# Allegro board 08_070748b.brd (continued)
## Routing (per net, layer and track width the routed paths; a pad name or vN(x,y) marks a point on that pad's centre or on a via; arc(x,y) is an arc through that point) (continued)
GND_POWER: length 1047
  TOP w0.203: 92.23,78.26 v2(92.26,78.26) 92.26,78.3 ; v2(89.26,81.26) 89.26,81.26
  LAYER_4 w0.254: v1(171.32,15.75) 170.43,14.86 170.43,14.22 173.99,10.67 J2.2 ; J1.4 179.32,148.84 178.94,148.46 178.94,147.32 175.51,143.89 175.51,139.57 v1(176.4,138.68) ; 124.33,10.8 124.33,13.21 106.05,31.5 CO29.1 106.93,67.44 v1(106.93,67.56) ; 7.95,76 7.19,76 ; J3.5 124.33,144.65 107.44,127.76 107.44,92.33 v1(106.93,91.82)
  LAYER_4 w0.508: P5.11 220.09,5.07 220.09,10.02 219.84,10.28 219.84,141.23 220.85,142.25 220.85,152.87 220.35,153.38 P4.11 P4.12 ; J2.2 J2.3 J2.4 J2.5 ; 220.31,4.83 220.31,2.83 ; 124.33,10.8 J6.2 J6.5 J6.4 J6.3 ; J3.4 J3.3 J3.2 J3.5 ; J1.5 J1.2 J1.3 J1.4
  LAYER_5 w0.254: v1(155.32,86.11) 155.45,86.11 156.46,85.09 168.28,85.09 168.91,85.72 v1(169.67,85.72) ; v1(106.05,67.56) 106.05,67.44 106.55,66.93 108.84,66.93 109.98,65.79 130.56,65.79 149.1,47.24 149.1,46.48 149.35,46.23 150.5,46.23 154.18,49.91 183.51,49.91 192.15,41.27 192.15,32.55 v1(192.19,32.51) ; J4.5 186.56,79.88 180.97,79.88 180.32,80.53 109.84,80.53 108.39,81.98 107.12,81.98 v1(107.06,82.04) ; J5.2 191.13,73.03 185.8,78.36 109.22,78.36 107.82,76.96 v1(107.06,76.96) ; v1(191.77,127.63) 191.64,127.51 191.64,113.41 189.87,111.63 167.39,111.63 164.72,108.97 154.56,108.97 151.89,111.63 148.34,111.63 139.83,103.12 120.65,103.12 110.87,93.34 105.41,93.34 105.03,92.96 v1(105.03,91.82)
  LAYER_5 w0.508: J5.2 J5.3 J5.4 J5.5 ; J4.5 J4.4 J4.3 J4.2
  LAYER_6 w0.254: v1(106.17,76.96) 106.86,77.85 107.82,77.85 108.08,77.6 108.08,76.96 109.35,75.69 v1(178.05,75.69) ; v1(178.05,83.19) 177.04,84.2 109.73,84.2 108.2,82.68 108.2,81.79 107.57,81.15 106.3,81.15 106.17,81.28 v1(106.17,82.04)
  BOTTOM w0.203: R74.2 176.66,138.43 v1(176.4,138.68) ; v1(83.44,65.66) 82.7,65.66 82.17,66.19 CIN11.1 v1(81.92,66.29) ; U3.7 v1(235.13,74.75) ; v1(226.44,115.7) 227.12,116.37 R182.1
  BOTTOM w0.254: v1(171.32,15.75) 171.45,15.88 R75.2 ; v1(178.05,75.69) 178.73,75.69 R20.2 ; v1(106.17,82.04) CO10.1 106.68,81.03 107.06,81.41 v1(107.06,82.04) ; R62.2 v1(191.77,127.63) ; 8.25,75.95 v1(7.11,75.95) ; R9.2 v1(192.19,32.51) ; CO37.1 170.43,86.49 v1(169.67,85.72) ; 76.33,79.76 v1(77.09,79.76) ; R122.1 v1(155.32,86.11) ; R64.2 v1(178.05,83.19)
  BOTTOM w0.305: v1(105.03,91.82) 105.03,92.71 105.16,92.84 CO2.1 106.43,92.84 106.93,92.33 v1(106.93,91.82) ; v1(106.05,67.56) CO29.1 106.93,67.44 v1(106.93,67.56)
  BOTTOM w0.381: R144.1 v1(195.07,11.52) ; v1(107.06,76.96) 107.06,77.6 106.68,77.98 CO20.1 v1(106.17,76.96) ; R183.1 226.86,109.35 226.86,109.01 v1(226.57,108.71) ; Q5.2 v1(90.5,146.81) ; v1(93.85,149.22) 94.59,149.22 94.95,148.87 Q8.2 ; J6.3 128.49,12.87 C74.2 ; R134.1 v1(83.95,11.64)
  BOTTOM w0.508: C71.2 128.74,146.9 J3.4 ; C73.2 197.19,75.22 J5.3 ; R180.1 v1(194.06,150.5) ; C91.1 v1(12.87,29.04) ; 227.08,138.18 v1(227.09,138.19) R181.1 ; v2(83.27,76.26) 83.07,76.45 CIN13.1 ; Q13.2 v1(93.04,8.71) ; CIN14.1 83.02,72.01 v2(83.27,72.26) ; 81.28,149.22 v1(81.28,150.24) ; C89.1 v1(12.87,143.34) ; v2(83.27,88.26) 83.26,88.27 CIN10.1 ; CIN9.1 82.94,82.93 v2(83.27,83.26) ; C72.2 198.46,95.16 199.52,94.11 J4.3 ; R52.2 v1(22.86,151.38)
  vias: v1(7.11,77.09) v1(7.11,74.8) v1(9.4,77.09) v1(9.4,75.95) v1(9.4,74.8) v1(12.23,124.46) v1(12.23,10.16) v1(16.64,77.09) v1(16.64,75.95) v1(16.64,74.8) v1(18.92,77.09) v1(18.92,75.95) v1(18.92,74.8) v1(25.53,112.14) v1(25.53,111) v1(25.53,109.86) v1(25.53,49.78) v1(25.53,48.64) v1(25.53,47.5) v1(27.81,112.14) v1(27.81,111) v1(27.81,109.86) v1(27.81,49.78) v1(27.81,48.64) v1(27.81,47.5) v1(30.48,42.29) v1(30.48,40.39) v1(31.75,117.22) v1(31.75,115.32) v1(32.26,110.11) v1(32.26,49.4) v1(32.38,42.29) v1(32.38,40.39) v1(33.02,110.11) v1(33.02,49.4) v1(33.66,117.22) v1(33.66,115.32) v1(33.78,110.11) v1(33.78,49.4) v1(34.29,42.29) v1(34.29,40.39) v1(35.56,117.22) v1(35.56,115.32) v1(36.2,42.29) v1(36.2,40.39) v1(37.47,117.22) v1(37.47,115.32) v1(38.1,42.29) v1(38.1,40.39) v1(39.37,117.22) v1(39.37,115.32) v1(39.88,10.29) v1(40.01,42.29) v1(40.01,40.39) v1(41.27,117.22) v1(41.27,115.32) v1(43.05,147.07) v1(81.92,93.85) v1(81.92,93.22) v1(81.92,92.58) v1(81.92,66.93) v1(81.92,65.66) v1(83.44,93.85) v1(83.44,93.22) v1(83.44,92.58) v1(83.44,66.93) v1(83.44,66.29) v1(88.6,9.95) v1(96.52,59.44) v1(96.52,57.53) v1(96.52,55.63) v1(96.52,53.72) v1(96.52,51.82) v1(96.52,49.91) v1(97.41,91.82) v1(97.54,82.04) v1(97.54,77.22) v1(97.54,67.56) v1(98.42,91.82) v1(98.42,82.04) v1(98.42,77.22) v1(98.42,67.56) v1(98.42,59.44) v1(98.42,57.53) v1(98.42,55.63) v1(98.42,53.72) v1(98.42,51.82) v1(98.42,49.91) v1(99.31,91.82) v1(99.31,82.04) v1(99.31,77.22) v1(99.31,67.56) v1(101.22,91.82) v1(101.35,82.04) v1(101.35,77.22) v1(101.35,67.56) v1(101.6,112.14) v1(101.6,110.24) v1(101.6,108.33) v1(101.6,106.43) v1(101.6,104.52) v1(101.6,102.62) v1(102.23,91.82) v1(102.23,82.04) v1(102.23,77.22) v1(102.23,67.56) v1(103.12,91.82) v1(103.12,82.04) v1(103.12,77.22) v1(103.12,67.56) v1(103.5,112.14) v1(103.5,110.24) v1(103.5,108.33) v1(103.5,106.43) v1(103.5,104.52) v1(103.5,102.62) v1(105.16,67.56) v1(105.28,82.04) v1(105.28,77.22) v1(106.05,91.82) v1(113.41,79.76) v1(114.3,79.76) v1(115.19,79.76) v1(118.49,79.76) v1(119.38,79.76) v1(120.27,79.76) v1(123.57,79.76) v1(124.46,79.76) v1(125.35,79.76) v1(128.52,127.76) v1(128.65,79.76) v1(128.65,31.88) v1(129.54,127.76) v1(129.54,79.76) v1(129.54,31.88) v1(130.43,127.76) v1(130.43,79.76) v1(130.43,31.88) v1(134.24,127.76) v1(134.37,79.76) v1(134.37,31.75) v1(135.25,127.76) v1(135.25,79.76) v1(135.25,31.75) v1(136.14,127.76) v1(136.14,79.76) v1(136.14,31.75) v1(139.19,127.76) v1(139.45,31.75) v1(140.21,127.76) v1(140.34,31.75) v1(141.1,127.76) v1(141.22,31.75) v1(144.4,127.76) v1(144.65,31.75) v1(145.41,127.76) v1(145.54,31.75) v1(146.3,127.76) v1(146.43,31.75) v1(149.48,127.76) v1(149.61,31.75) v1(150.5,127.76) v1(150.5,31.75) v1(151.38,127.76) v1(151.38,31.75) v1(153.92,126.87) v1(154.05,32.64) v1(154.94,126.87) v1(154.94,32.64) v1(155.15,153.67) v1(155.83,126.87) v1(155.83,32.64) v1(155.92,5.84) v1(178.05,131.19) v1(178.05,130.43) v1(178.05,129.67) v1(178.05,128.14) v1(178.05,127.38) v1(178.05,126.62) v1(178.05,124.33) v1(178.05,123.57) v1(178.05,122.81) v1(178.05,36.2) v1(178.05,35.43) v1(178.05,34.67) v1(178.05,32.51) v1(178.05,31.75) v1(178.05,30.99) v1(178.05,29.46) v1(178.05,28.7) v1(178.05,27.94) v1(201.3,122.94) v1(201.3,121.03) v1(201.3,119.13) v1(201.3,117.22) v1(201.3,115.32) v1(201.3,113.41) v1(201.3,45.47) v1(201.3,43.56) v1(201.3,41.66) v1(201.3,39.75) v1(201.3,37.85) v1(201.3,35.94) v1(203.2,122.94) v1(203.2,121.03) v1(203.2,119.13) v1(203.2,117.22) v1(203.2,115.32) v1(203.2,113.41) v1(203.2,45.47) v1(203.2,43.56) v1(203.2,41.66) v1(203.2,39.75) v1(203.2,37.85) v1(203.2,35.94) v1(230.25,71.88) v2(81.27,90.26) v2(81.27,89.26) v2(81.27,85.26) v2(81.27,81.26) v2(81.27,80.26) v2(81.27,79.26) v2(81.27,78.26) v2(81.27,74.26) v2(81.27,70.26) v2(81.27,69.26) v2(82.27,90.26) v2(82.27,89.26) v2(82.27,85.26) v2(82.27,81.26) v2(82.27,80.26) v2(82.27,79.26) v2(82.27,78.26) v2(82.27,74.26) v2(82.27,70.26) v2(82.27,69.26) v2(83.27,90.26) v2(83.27,89.26) v2(83.27,87.26) v2(83.27,86.26) v2(83.27,85.26) v2(83.27,84.26) v2(83.27,82.26) v2(83.27,81.26) v2(83.27,80.26) v2(83.27,79.26) v2(83.27,78.26) v2(83.27,77.26) v2(83.27,75.26) v2(83.27,74.26) v2(83.27,73.26) v2(83.27,71.26) v2(83.27,70.26) v2(83.27,69.26) v2(84.27,90.26) v2(84.27,89.26) v2(84.27,88.26) v2(84.27,87.26) v2(84.27,86.26) v2(84.27,85.26) v2(84.27,84.26) v2(84.27,83.26) v2(84.27,82.26) v2(84.27,81.26) v2(84.27,80.26) v2(84.27,79.26) v2(84.27,78.26) v2(84.27,77.26) v2(84.27,76.26) v2(84.27,75.26) v2(84.27,74.26) v2(84.27,73.26) v2(84.27,72.26) v2(84.27,71.26) v2(84.27,70.26) v2(84.27,69.26) v2(85.27,80.26) v2(85.27,79.26) v2(86.27,80.26) v2(86.27,79.26) v2(87.27,90.26) v2(87.27,89.26) v2(87.27,88.26) v2(87.27,87.26) v2(87.27,86.26) v2(87.27,85.26) v2(87.27,84.26) v2(87.27,83.26) v2(87.27,81.26) v2(87.27,80.26) v2(87.27,79.26) v2(87.27,78.26) v2(87.27,77.26) v2(87.27,76.26) v2(87.27,75.26) v2(87.27,74.26) v2(87.27,73.26) v2(87.27,72.26) v2(87.27,71.26) v2(87.27,70.26) v2(87.27,69.26) v2(88.27,81.26) v2(88.27,80.26) v2(88.27,79.26) v2(89.26,80.26) v2(89.26,79.26) v2(90.26,81.26) v2(90.26,80.26) v2(91.26,81.26) v2(91.26,80.26) v2(92.26,90.26) v2(92.26,89.26) v2(92.26,88.26) v2(92.26,87.26) v2(92.26,86.26) v2(92.26,85.26) v2(92.26,84.26) v2(92.26,83.26) v2(92.26,82.26) v2(92.26,81.26) v2(92.26,80.26) v2(92.26,79.26) v2(92.26,76.26) v2(92.26,75.26) v2(92.26,74.26) v2(92.26,73.26) v2(92.26,72.26) v2(92.26,71.26) v2(92.26,70.26) v2(92.26,69.26) v2(93.26,80.26) v2(93.26,79.26) v2(94.26,80.26) v2(94.26,79.26) v2(95.26,80.26) v2(95.26,79.26)
SVIN_01: length 16.3
  TOP w0.152: 88.27,82.19 U1.J8
  TOP w0.254: v2(87.91,81.89) 88.27,82.19
  LAYER_3 w0.152: 80.77,81.77 86.47,81.77 86.58,81.89 v2(87.91,81.89)
  LAYER_3 w0.203: 80.77,81.77 74.51,81.77 v1(74.4,81.89)
  BOTTOM w0.152: C26.2 87.91,81.93 v2(87.91,81.89)
  BOTTOM w0.203: 74.38,81.9 v1(74.4,81.89) ; 74.38,81.9 R32.1 ; 74.38,81.9 R142.1
SVIN_23: length 22.5
  LAYER_3 w0.152: v2(91.26,77.26) 90.75,76.74 90.75,76.06 90.47,75.77 90.06,75.77 89.75,75.46 89.75,75.06 89.47,74.77 80.93,74.77 80.77,74.93
  LAYER_3 w0.203: v1(74.38,75.48) 80.22,75.48 80.77,74.93
  BOTTOM w0.203: R143.1 v1(74.38,75.48) ; v2(91.26,77.26) 92.16,77.26 C27.2
  BOTTOM w0.508: R143.1 R33.1
VDD25_01: length 75.4
  LAYER_4 w0.508: v1(80.01,120.61) 80.01,151.13 TP29.1
  LAYER_6 w0.381: v1(87.63,120.65) 86.98,120 86.98,117.97 87.3,117.66 87.3,92.81 87.68,92.43 v1(88.06,92.43)
  BOTTOM w0.152: v2(88.27,88.26) 87.78,88.74 87.78,90.81
  BOTTOM w0.203: 88.14,92.42 88.14,91.19 87.78,90.83 87.78,90.81
  BOTTOM w0.508: v1(87.63,120.61) R59.2 R58.2 R55.2 v1(80.01,120.61)
VDD25_23: length 80.4
  LAYER_3 w0.508: v1(96.52,38.86) 97.54,39.88 97.54,45.21 94.87,47.88 v1(94.87,67.04)
  LAYER_6 w0.508: TP30.1 95.89,17.91 95.89,38.23 v1(96.52,38.86)
  BOTTOM w0.203: v1(94.87,67.04) 94.87,67.56 94.11,68.33 92.23,68.33 91.3,69.26 v2(91.26,69.26)
  BOTTOM w0.508: R11.1 R12.1 R15.1 R14.1 R13.1
VDD33_01: length 526
  LAYER_3 w0.152: 80.77,86.74 87.76,86.74 88.24,86.26 v2(88.27,86.26)
  LAYER_3 w0.203: 80.77,86.74 75.82,86.74 v1(75.56,86.49)
  LAYER_4 w0.203: v1(217.55,144.78) 217.34,144.99 217.34,151.82 217.54,152.02 v1(217.55,152.02)
  LAYER_4 w0.381: v1(225.04,54.86) 225.04,54.99 225.25,55.2 ; v1(226.31,46.23) 225.59,46.95 225.59,54.86 225.25,55.2 ; 225.25,55.2 224.03,56.43 224.03,126.33 v1(225.59,127.89) 225.59,132.14 v1(226.95,133.5) 226.06,134.39 226.06,143.89 226.44,144.27 231.65,144.27 v1(232.28,143.64) ; v1(75.56,86.49) 75.82,86.74 79.12,86.74 80.39,88.01 80.39,114.43 76.84,117.98 76.84,144.14 TP27.1
  LAYER_4 w0.508: v1(3.43,142.24) v1(3.43,124.46)
  LAYER_5 w0.381: v1(230.57,54.86) v1(225.04,54.86) ; v1(225.59,127.89) 230.04,127.89 v1(230.12,127.8)
  LAYER_5 w0.508: 67.31,156.46 v1(90.42,156.46) 122.43,156.46 123.19,157.23 201.68,157.23 206.88,152.02 v1(217.55,152.02) 231.01,152.02 231.45,151.58 233.1,151.58 235.08,149.61 235.08,146.43 v1(232.28,143.64) ; 67.31,156.46 43.69,156.46 43.53,156.3 v1(42.77,156.3) 41.21,157.86 24.38,157.86 22.09,155.56 22.09,152.9 16.76,147.57 16.76,145.8 12.95,141.99 4.45,141.99 4.19,142.24 v1(3.43,142.24) ; 67.31,156.46 TP27.1
  BOTTOM w0.152: 88.75,90.64 88.75,86.74 v2(88.27,86.26)
  BOTTOM w0.203: R60.2 217.34,144.31 217.55,144.53 v1(217.55,144.78) ; 88.75,90.64 88.75,90.78 89.03,91.06 89.09,91.06
  BOTTOM w0.254: 229.62,133.48 D1.C
  BOTTOM w0.381: v1(226.95,133.5) 226.97,133.48 229.62,133.48 ; v1(226.31,46.23) R68.2 R53.2 ; v1(230.57,54.86) R51.2 ; C39.2 89.66,91.63 89.09,91.06 ; v1(90.42,156.46) R66.2 R67.2
  BOTTOM w0.508: R127.2 v1(3.43,124.46) ; TP27.1 73.03,147.95 74.42,147.95 74.55,147.83 76.58,147.83 76.59,147.82 Q7.2 ; v1(230.12,127.8) R71.2 ; R70.2 v1(42.77,156.3) ; v1(3.43,142.24) R133.2
VDD33_23: length 518.7
  LAYER_3 w0.508: TP28.1 78.39,5.84 82.42,9.88 82.42,11.94 89.66,19.18 89.66,66.08 v1(88.65,67.09)
  LAYER_4 w0.381: v1(226.19,13.08) 226.19,38.23 v1(228.22,40.26) 227.08,41.4 227.08,46.77 226.69,47.15 v1(226.69,47.75) 226.57,47.75 226.17,48.15 226.17,56.39 225.43,57.14 225.43,125.35 227.2,127.13 227.27,127.13 ; 227.27,127.13 227.27,131.91 v1(227.2,131.98) ; 227.27,127.13 227.27,108.49 227.2,108.43 v1(227.2,107.7)
  LAYER_4 w0.508: v1(4.87,27.94) 4.32,27.94 3.81,27.43 3.81,10.54 5.12,9.23 v1(9.1,9.23) ; v1(226.19,13.08) 226.19,12.32 226.22,12.29 v1(226.22,6.73)
  LAYER_5 w0.381: v1(226.19,13.08) 226.07,13.2 222.4,13.2 222.39,13.21 222,13.21 213.74,21.46 v1(213.27,21.46)
  LAYER_5 w0.508: v1(9.1,9.23) 9.87,9.23 10.21,8.89 v1(30.48,8.89) 30.48,3.3 30.99,2.79 77.47,2.79 ; 77.47,2.79 TP28.1 ; 77.47,2.79 90.17,2.79 90.42,3.05 ; 90.42,3.05 90.42,2.92 91.44,1.91 197.36,1.91 202.18,6.73 v1(226.22,6.73) ; 90.42,3.05 v1(90.42,3.81)
  BOTTOM w0.152: v2(90.26,71.26) 90.08,71.26 89.56,70.74 89.07,70.74 88.78,70.46 88.78,69.09 88.65,68.95 88.65,68.71
  BOTTOM w0.203: v1(88.65,67.09) 88.65,68.71
  BOTTOM w0.381: R16.2 v1(226.19,13.08) ; R21.2 228.17,40.21 v1(228.22,40.26) ; v1(227.2,131.98) 229.26,131.98 229.29,131.95 D2.C ; v1(227.2,107.7) R2.2 ; R28.2 v1(226.69,47.75) ; v1(213.27,21.46) R6.2 ; R4.2 TP28.1
  BOTTOM w0.508: R2.2 231.56,107.61 R1.2 ; R138.2 v1(9.1,9.23) ; TP28.1 77.27,6.04 Q10.2 ; R5.1 R7.1 v1(90.42,3.81) ; R3.2 v1(30.48,8.89)
VIN: length 478.7
  LAYER_4 w0.381: v1(64.64,21.76) 64.64,50.8 63.5,51.94 v1(63.5,52.32) ; v1(81.28,11.64) v1(81.28,21.72)
  LAYER_4 w0.508: v1(63.88,81.15) 63.88,98.55 63.5,98.93 v1(63.5,99.31) ; v1(63.88,78.11) 63.88,60.96 63.24,59.99 v1(63.25,59.94) ; v1(84.2,149.22) 84.2,153.29 80.64,156.84 54.61,156.84 53.09,155.32 53.09,108.71 56.13,105.66 v1(62.1,105.66) ; v1(25.53,103.89) 19.56,109.86 19.56,155.26 v1(20.61,156.3)
  LAYER_5 w0.381: v1(65.41,98.17) 65.41,100.46 v1(64.77,101.09) ; v1(65.41,61.59) 66.04,60.96 66.04,58.68 65.66,58.3 v1(64.77,58.29) ; v1(222.67,13.84) 214.4,22.11 85.86,22.11 85.47,21.72 v1(81.28,21.72) 64.68,21.72 v1(64.64,21.76)
  LAYER_5 w0.508: v1(71.75,81.15) v1(63.88,81.15) ; v1(63.88,78.11) v1(71.75,78.11) ; v1(18.92,82.8) 19.43,82.8 22.61,79.63 v1(71.75,79.63)
  BOTTOM w0.381: v1(64.77,58.29) 64.57,58.22 63.3,58.22 ; CIN3.P 25.61,103.97 v1(25.53,103.89) ; R38.2 v1(65.41,61.59) ; R34.2 v1(65.41,98.17) ; R155.1 v1(222.67,13.84) ; v1(64.77,101.09) R35.1
  BOTTOM w0.508: 72.68,79.63 v1(71.75,79.63) ; R33.2 v1(71.75,78.11) ; R43.2 v1(20.61,156.3) ; R32.2 v1(71.75,81.15) ; 83.19,149.22 v1(84.2,149.22)
  vias: v1(7.11,84.07) v1(7.11,82.8) v1(7.11,81.53) v1(9.4,84.07) v1(9.4,82.8) v1(9.4,81.53) v1(16.64,84.07) v1(16.64,82.8) v1(16.64,81.53) v1(18.92,84.07) v1(18.92,81.53) v1(25.53,105.16) v1(25.53,102.62) v1(25.53,56.77) v1(25.53,55.5) v1(25.53,54.23) v1(27.81,105.16) v1(27.81,103.89) v1(27.81,102.62) v1(27.81,56.77) v1(27.81,55.5) v1(27.81,54.23) v1(32.26,105.28) v1(32.26,54.23) v1(33.02,105.28) v1(33.02,54.23) v1(33.78,105.28) v1(33.78,54.23) v1(47.62,107.06) v1(47.62,105.16) v1(47.62,103.25) v1(47.62,101.35) v1(47.62,99.44) v1(47.62,97.54) v1(47.62,63.25) v1(47.62,61.34) v1(47.62,59.44) v1(47.62,57.53) v1(47.62,55.63) v1(47.62,53.72) v1(49.53,107.06) v1(49.53,105.16) v1(49.53,103.25) v1(49.53,101.35) v1(49.53,99.44) v1(49.53,97.54) v1(49.53,63.25) v1(49.53,61.34) v1(49.53,59.44) v1(49.53,57.53) v1(49.53,55.63) v1(49.53,53.72) v1(51.44,107.06) v1(51.44,105.16) v1(51.44,103.25) v1(51.44,101.35) v1(51.44,99.44) v1(51.44,97.54) v1(51.44,63.25) v1(51.44,61.34) v1(51.44,59.44) v1(51.44,57.53) v1(51.44,55.63) v1(51.44,53.72) v1(61.98,102.49) v1(61.98,101.22) v1(61.98,99.82) v1(61.98,59.56) v1(61.98,58.29) v1(61.98,56.9) v1(61.98,54.74) v1(61.98,53.34) v1(61.98,52.2) v1(62.1,106.93) v1(62.1,104.27)
VIN01: length 6.7
  LAYER_5 w0.381: v1(67.31,98.04) 67.31,100.58 v1(67.82,101.09)
  BOTTOM w0.381: R35.2 v1(67.82,101.09) ; R37.2 v1(67.31,98.04)
  BOTTOM w0.508: v2(86.27,88.26) 86.26,88.27 CIN10.2 ; v2(86.27,83.26) 85.94,82.93 CIN9.2
  vias: v1(70.61,107.19) v1(70.61,105.92) v1(70.61,104.52) v1(70.61,102.36) v1(70.61,101.09) v1(70.61,99.69) v1(81.92,107.06) v1(81.92,105.16) v1(81.92,103.25) v1(81.92,101.35) v1(81.92,99.44) v1(83.82,107.06) v1(83.82,105.16) v1(83.82,103.25) v1(83.82,101.35) v1(83.82,99.44) v1(85.22,93.85) v1(85.22,93.22) v1(85.22,92.58) v1(85.72,107.06) v1(85.72,105.16) v1(85.72,103.25) v1(85.72,101.35) v1(85.72,99.44) v2(85.27,90.26) v2(85.27,89.26) v2(85.27,88.26) v2(85.27,87.26) v2(85.27,86.26) v2(85.27,85.26) v2(85.27,84.26) v2(85.27,83.26) v2(85.27,82.26) v2(85.27,81.26) v2(86.27,90.26) v2(86.27,89.26) v2(86.27,87.26) v2(86.27,86.26) v2(86.27,85.26) v2(86.27,84.26) v2(86.27,82.26) v2(86.27,81.26)
VIN23: length 9.2
  TOP w0.203: v2(86.27,78.26) 86.23,78.26
  LAYER_5 w0.381: v1(67.31,61.62) 66.67,60.99 66.67,58.67 67.18,58.17 v1(68.2,58.17)
  BOTTOM w0.203: v1(85.22,66.29) CIN11.2
  BOTTOM w0.381: v1(68.2,58.17) R39.2 69.61,58.17 ; R41.2 v1(67.31,61.62)
  BOTTOM w0.508: CIN13.2 86.07,76.45 v2(86.27,76.26) ; v2(86.27,72.26) 86.02,72.01 CIN14.2
  vias: v1(70.61,59.56) v1(70.61,58.17) v1(70.61,56.9) v1(70.61,54.86) v1(70.61,53.47) v1(70.61,52.2) v1(80.64,60.07) v1(80.64,58.17) v1(80.64,56.26) v1(80.64,54.36) v1(80.64,52.45) v1(82.55,60.07) v1(82.55,58.17) v1(82.55,56.26) v1(82.55,54.36) v1(82.55,52.45) v1(84.45,60.07) v1(84.45,58.17) v1(84.45,56.26) v1(84.45,54.36) v1(84.45,52.45) v1(85.22,67.06) v1(85.22,65.53) v2(85.27,78.26) v2(85.27,77.26) v2(85.27,76.26) v2(85.27,75.26) v2(85.27,74.26) v2(85.27,73.26) v2(85.27,72.26) v2(85.27,71.26) v2(85.27,70.26) v2(85.27,69.26) v2(86.27,77.26) v2(86.27,75.26) v2(86.27,74.26) v2(86.27,73.26) v2(86.27,71.26) v2(86.27,70.26) v2(86.27,69.26)
ALERTB: length 260.6
  LAYER_4 w0.203: P3.B3 236.35,86.99 236.35,39.2 TP50.1 ; P4.3 v1(212.34,150.24) 212.34,147.73 211.66,147.04 211.66,146.58 211.96,146.28 211.96,141.45 212.09,141.32 212.09,24.64 211.9,24.45 211.9,23.56 212.09,23.37 212.09,19.33 211.82,19.07 211.82,13.98 212.17,13.64 212.17,6.11 212.33,5.94 P5.3
  LAYER_5 w0.203: v1(215.26,7.75) 215.65,7.37 230.76,7.37 234.31,10.92 234.31,32.93 TP50.1
  BOTTOM w0.203: R157.1 212.32,149.32 v1(212.34,150.24) ; R156.1 216.33,8.83 215.26,7.76 ; 215.26,7.76 P5.3 ; 215.26,7.76 v1(215.26,7.75)
ALERTB_01: length 348.4
  LAYER_4 w0.203: v1(217.68,12.06) v1(217.68,45.34) 217.42,45.59 217.42,57.28 217.81,57.66 217.81,58.93 217.42,59.31 217.42,138.05 v1(217.55,138.18)
  LAYER_5 w0.203: v1(217.68,12.06) 217.68,11.5 214.31,8.13 199.39,8.13 197.1,5.84 TP44.1 ; v1(229.11,46.23) 228.22,45.34 v1(217.68,45.34) ; v1(95.25,138.18) 171.83,138.18 172.72,137.29 177.17,137.29 178.05,138.18 v1(217.55,138.18)
  LAYER_6 w0.152: v2(91.26,88.26) 91.26,88.57 91.75,89.06 91.75,90.44 92.08,90.77 92.08,90.81
  LAYER_6 w0.203: v1(95.25,138.18) 95.25,135.25 92.08,132.08 92.08,97.85 92.15,97.77 92.15,96.97 92.08,96.89 92.08,90.81
  BOTTOM w0.203: R156.2 216.37,12.06 v1(217.68,12.06)
  BOTTOM w0.381: Q15.1 189.6,6.48 190.25,5.84 TP44.1
ALERTB_23: length 370
  LAYER_4 w0.203: v1(212.22,146.81) 212.6,146.43 v1(212.6,24) ; v1(72.39,8.38) v1(72.39,24) 72.39,48.49 73.15,49.25 v1(73.15,70.74)
  LAYER_5 w0.152: 80.77,71.75 87.76,71.75 v2(88.27,72.26)
  LAYER_5 w0.203: v1(73.15,70.74) 73.53,71.12 77.96,71.12 78.13,71.29 78.59,71.29 78.76,71.12 80.01,71.12 80.64,71.75 80.77,71.75 ; TP45.1 198.5,148.21 208.28,148.21 209.68,146.81 v1(212.22,146.81) ; v1(72.39,24) 72.52,24.13 212.47,24.13 v1(212.6,24)
  BOTTOM w0.203: R4.1 v1(72.39,8.38) ; R157.2 212.31,146.9 v1(212.22,146.81)
  BOTTOM w0.508: TP45.1 191.9,152.53 Q9.1
AUXP: length 210.7
  LAYER_4 w0.102: P5.8 216.33,3 215.32,4.01 215.32,5.79 215.37,5.84
  LAYER_4 w0.203: TP47.1 230,60.11 230,69.98 v1(231.9,71.88) ; v1(232.58,79.63) 232.58,80.34 231.51,81.41 231.51,91.69 P3.A1 ; P4.8 215.33,155.59 215.33,154.17 216.33,153.17 216.33,144.12 216.37,144.08 216.37,143.62 216.28,143.53 216.28,58.55 v1(216.66,58.17) 216.28,57.78 216.28,29.21 216.54,28.96 216.54,27.18 216.28,26.92 216.28,6.76 215.37,5.84
  LAYER_5 w0.203: v1(216.66,58.17) 216.92,57.91 TP47.1
  BOTTOM w0.203: C14.1 231.85,73.03 232.92,74.1 ; v1(232.58,79.63) R19.2 232.58,74.44 232.92,74.1 ; 232.92,74.1 U3.8
AUXSCL: length 10.3
  BOTTOM w0.203: U3.6 235.03,75.4 235.58,75.96 235.58,78.94 234.9,79.63 R18.1 234.28,81.06 P3.A6
AUXSDA: length 9.3
  LAYER_4 w0.203: P3.B6 234.58,77.22 v1(234.19,76.83)
  BOTTOM w0.203: U3.5 233.97,76.44 234.28,76.74 R19.1 234.19,77.89 v1(234.19,76.83)
COMP0A: length 15.3
  BOTTOM w0.152: v2(91.26,84.26) 91.78,84.77 91.78,85.46 92.1,85.77 92.47,85.77 92.78,86.09 92.78,90.75 92.84,90.81
  BOTTOM w0.203: 92.84,90.81 93.09,91.06 95,91.06 95.76,91.82 C48.1 95.78,92.42 96.56,93.19 96.56,94.87 96.42,95.01 96.42,95.11 95.86,95.67 R81.1
COMP0B: length 11.1
  BOTTOM w0.152: 91.82,90.81 91.75,90.73 91.75,85.92 91.56,85.74 91.06,85.74 90.78,85.46 90.78,84.56 90.48,84.26 v2(90.26,84.26)
  BOTTOM w0.203: C49.1 93.51,92.42 93.46,92.37 R82.1 92.71,91.69 91.82,90.81
COMP1A: length 17.7
  LAYER_6 w0.152: 92.78,90.81 92.78,89.06 92.47,88.74 92.06,88.74 91.75,88.42 91.75,86.06 91.43,85.74 91.06,85.74 90.78,85.46 90.78,85.09 90.43,84.74 89.75,84.74 v2(89.26,84.26)
  LAYER_6 w0.203: v1(92.71,95.67) 92.71,91 92.78,90.92 92.78,90.81
  BOTTOM w0.203: v1(92.71,95.67) 92.81,95.67 93.37,96.23 93.37,96.53 94.21,97.37 C50.1 R81.2
COMP1B: length 12.6
  BOTTOM w0.152: 90.04,90.81 89.78,90.54 89.78,85.77 v2(89.26,85.26)
  BOTTOM w0.203: 92.61,94.07 92.05,93.51 92.05,93.26 91.21,92.42 C51.1 91.16,92.42 90.53,91.79 90.53,91.29 90.04,90.81 ; 92.61,94.07 91.84,94.83 91.84,95.11 91.29,95.67 R99.1 ; 92.61,94.07 R82.2
COMP2A: length 96.9
  LAYER_4 w0.203: v1(70.74,62.1) 71.12,62.48 71.12,75.18 ; 71.12,75.18 v1(70.61,75.18) ; 71.12,75.18 71.12,81.31 71.25,81.44 v1(71.25,98.17)
  LAYER_5 w0.152: 80.77,75.45 81.06,75.74 87.78,75.74 v2(88.27,75.26)
  LAYER_5 w0.203: v1(88.65,62.19) 88.56,62.1 v1(70.74,62.1) ; v1(92.71,98.17) v1(71.25,98.17) ; 80.77,75.45 80.15,74.83 72.46,74.83 72.23,75.06 70.74,75.06 v1(70.61,75.18)
  BOTTOM w0.203: v1(88.65,62.19) R110.1 ; R98.2 v1(92.71,98.17)
COMP2B: length 74.7
  LAYER_4 w0.203: v1(70.23,74.42) 69.98,74.68 69.98,75.82 70.61,76.45 70.61,97.33 v1(70.65,97.37)
  LAYER_5 w0.152: 80.77,74.45 81.06,74.74 88.75,74.74 v2(89.26,75.26)
  LAYER_5 w0.203: v1(91.19,97.37) v1(70.65,97.37) ; 80.77,74.45 80.75,74.42 v1(70.23,74.42)
  BOTTOM w0.152: v2(89.26,75.26) 89.78,74.74 89.78,73.93 89.93,73.77 90.6,73.77 90.75,73.62 90.75,71.06 90.47,70.77 90.46,70.77 90.42,70.74 90.06,70.74 89.78,70.46 89.78,68.71
  BOTTOM w0.203: R111.1 C2.2 90.17,67.79 89.78,68.18 89.78,68.71
COMP3A: length 12.3
  LAYER_6 w0.152: 91.78,68.71 91.78,72.55 91.31,73.02 91.31,73.21 v2(91.26,73.26)
  LAYER_6 w0.203: 91.78,68.71 91.78,64.68 v1(92.58,63.88)
  BOTTOM w0.203: v1(92.58,63.88) 91.7,63.88 C18.2 R110.2
COMP3B: length 10.4
  BOTTOM w0.152: 90.76,68.71 90.76,69.47 91.05,69.76 91.46,69.76 91.75,70.06 91.75,71.77 v2(91.26,72.26)
  BOTTOM w0.203: 93.32,67.04 92.69,66.41 92.69,66.39 92.35,66.05 92.35,65.95 91.8,65.39 R111.2 ; 93.32,67.04 C19.2 ; 93.32,67.04 92.57,67.79 91.08,67.79 90.76,68.12 90.76,68.71
FAULT0B: length 355.2
  LAYER_4 w0.152: 91.39,90.81 91.26,90.68 v2(91.26,90.26)
  LAYER_4 w0.203: v1(209.42,124.33) 209.42,14.2 209.68,13.94 v1(209.68,13.33) ; v1(231.9,124.71) 231.65,124.97 231.65,129.54 ; 231.65,129.54 v1(231.27,129.54) ; 231.65,129.54 231.65,138.16 232.2,138.71 TP40.1 ; v1(91.26,141.73) 91.26,140.41 90.04,139.19 90.04,118.75 91.69,117.09 91.69,97.65 91.74,97.6 91.74,97.14 91.72,97.11 91.72,91.13 91.39,90.81
  LAYER_5 w0.203: v1(91.26,141.73) 91.9,141.73 91.95,141.68 207.21,141.68 v1(207.64,142.11) 210.72,142.11 212.12,140.72 230.19,140.72 230.32,140.59 TP40.1 ; v1(231.9,124.71) 231.52,124.33 v1(209.42,124.33)
  BOTTOM w0.203: TP40.1 229.84,142.94 Q12.1 ; R69.1 230.16,129.54 v1(231.27,129.54) ; R167.1 210.22,12.79 v1(209.68,13.33) ; R176.2 206.72,143.3 207.01,143 D3.A 207.64,142.96 v1(207.64,142.11)
  BOTTOM w0.254: R84.1 v1(231.9,124.71)
FAULT1B: length 338.8
  LAYER_4 w0.152: v2(90.26,90.26) 90.3,90.29 90.3,90.81
  LAYER_4 w0.203: v1(211.07,140.97) 210.95,140.84 210.95,127.71 210.64,127.41 210.64,119.79 210.92,119.51 210.92,119.11 210.95,119.09 v1(210.95,118.87) 210.95,118.66 210.92,118.63 210.92,118.24 210.77,118.09 210.77,13.64 v1(211.2,13.21) ; 90.3,90.81 90.3,90.87 90.63,91.2 90.63,91.26 90.81,91.44 90.81,95.81 90.17,96.45 90.17,112.14 88.8,113.51 88.8,139.34 v1(90.3,140.84)
  LAYER_5 w0.203: v1(90.3,140.84) 210.95,140.84 v1(211.07,140.97) ; v1(210.95,118.87) TP41.1
  BOTTOM w0.203: Q14.1 229.12,121.33 R71.1 R84.2 231.9,119.17 TP41.1 R101.1 ; R164.2 211.75,12.66 v1(211.2,13.21) ; R177.2 211.49,142 211.07,141.58 v1(211.07,140.97)
  BOTTOM w0.381: D4.A 211.2,143 R177.2
FAULT2B: length 314.8
  LAYER_4 w0.203: v1(234.23,106.26) 234.23,101.65 234.28,101.6 234.28,98.13 231.1,94.96 231.1,75.35 234.61,71.84 234.61,40.3 229.62,35.31 229.62,9.14 v1(229.74,9.02)
  LAYER_5 w0.203: v1(229.74,9.02) 221.11,9.02 219.41,10.72 219.41,12.78 218.39,13.79 217.66,13.79 217.1,14.35 213.87,14.35 v1(212.72,13.21) 207.71,18.22 ; 207.71,18.22 205.52,20.41 105.35,20.41 105.13,20.19 v1(104.52,20.19) ; 207.71,18.22 207.09,17.6 207.09,17.53 206.88,17.32 v1(206.88,17.15)
  LAYER_6 w0.152: 94.81,68.71 94.75,68.77 93.06,68.77 92.78,69.06 92.78,73.46 92.47,73.77 90.78,73.77 v2(90.26,73.26)
  LAYER_6 w0.203: v1(104.52,20.19) 104.52,59 94.81,68.71
  BOTTOM w0.203: TP42.1 229.71,113.73 Q16.1 ; TP42.1 R101.2 ; TP42.1 233.17,110.28 R2.1 233.17,106.35 R113.1 v1(234.23,106.26) ; v1(212.72,13.21) 213.27,12.66 R165.2 ; R178.2 205.69,17.19 D5.A
FAULT3B: length 308.7
  LAYER_3 w0.152: v2(90.26,72.26) 89.78,71.77 89.78,68.71
  LAYER_3 w0.203: 89.78,68.71 89.78,67.3 89.8,67.3 91.57,65.53 91.57,18.54 v1(90.3,17.27)
  LAYER_4 w0.203: v1(214.12,13.08) 214.05,13.16 214.05,16.94 214.25,17.15 214.25,101.73 v1(213.87,102.11)
  LAYER_5 w0.203: TP43.1 230.57,100.84 229.3,102.11 v1(213.87,102.11) ; 199.77,14.22 201.42,14.22 203.71,11.94 212.98,11.94 v1(214.12,13.08) ; 199.77,14.22 199.77,16.64 200.66,17.53 v1(201.04,17.53) ; 199.77,14.22 176.02,14.22 173.1,17.15 v1(90.3,17.27)
  BOTTOM w0.203: v1(214.12,13.08) 214.27,12.94 214.52,12.94 214.8,12.66 R166.2 ; v1(201.04,17.53) R179.2 202.65,17.49 D6.A ; R113.2 R1.1 231.56,103.79 232.45,102.9 TP43.1 230.35,102.94 Q17.1
FAULTB: length 162
  LAYER_4 w0.203: v1(210.95,10.33) 210.32,10.33 210.31,10.33 ; P5.1 210.31,4.85 210.31,10.33 ; P4.1 210.44,154.46 210.44,149.99 v1(210.4,149.95) 210.4,146.05 210.24,145.89 210.24,86.79 210.26,86.76 210.26,10.38 210.31,10.33
  LAYER_5 w0.203: v1(207.68,149.35) 208.28,149.95 v1(210.4,149.95)
  BOTTOM w0.203: v1(210.4,149.95) 210.73,149.62 R173.1 ; R172.1 v1(207.68,149.35)
  BOTTOM w0.381: R166.1 R165.1 R164.1 v1(210.95,10.33) R167.2 R175.1 R174.1
INTVCC_01: length 94.8
  LAYER_3 w0.152: v2(89.26,82.26) 88.75,82.77 80.77,82.77
  LAYER_3 w0.203: v1(72.68,83.53) 73.44,82.77 80.77,82.77
  LAYER_4 w0.203: TP25.1 72.68,138.14 v1(72.68,83.53)
  BOTTOM w0.152: C38.2 89.19,82.33 v2(89.26,82.26)
  BOTTOM w0.203: R142.2 v1(72.68,83.53)
INTVCC_23: length 92.6
  LAYER_3 w0.152: 80.77,76.58 80.91,76.58 81.06,76.74 89.75,76.74 v2(90.26,77.26)
  LAYER_3 w0.203: v1(72.68,76.58) 80.77,76.58
  LAYER_4 w0.508: TP26.1 67.31,44.2 72.01,48.89 72.01,75.91 v1(72.68,76.58)
  BOTTOM w0.203: v2(90.26,77.26) 90.17,77.35 90.17,78.6 C41.2
PGOOD0: length 83.9
  LAYER_6 w0.152: 89.03,90.81 88.78,90.56 88.78,88.06 89.1,87.74 89.47,87.74 89.75,87.46 89.75,87.06 89.47,86.77 89.1,86.77 88.75,86.42 88.75,83.77 v2(89.26,83.26)
  LAYER_6 w0.203: TP36.1 92.18,153.67 92.38,153.47 v1(92.38,146.61) 92.38,140.64 92.68,140.34 92.68,135.86 90.17,133.35 90.17,115.85 90.12,115.8 90.12,115.34 90.17,115.29 90.17,94.3 90.22,94.25 90.22,93.79 90.13,93.7 90.13,91.91 89.03,90.81
  BOTTOM w0.381: Q5.1 v1(92.38,146.61)
  BOTTOM w0.508: R83.1 91.09,153.8 90.96,153.67 R66.1 TP36.1
PGOOD1: length 87.4
  LAYER_6 w0.152: 93.72,90.81 93.75,90.78 93.75,89.06 93.43,88.74 93.06,88.74 92.77,88.45 92.77,87.05 92.75,87.02 92.75,86.06 92.47,85.77 91.99,85.77 91.75,85.53 91.75,85.47 91.76,85.46 91.76,85.06 91.75,85.05 91.75,85.03 91.45,84.74 91.06,84.74 90.75,84.42 90.75,83.91 90.62,83.77 90.06,83.77 89.75,83.46 89.75,83.06 89.47,82.77 88.75,82.77 v2(88.27,83.26)
  LAYER_6 w0.203: TP37.1 96.82,152.7 v1(96.82,146.74) 96.82,135.31 92.48,130.96 92.48,99.19 93.34,98.33 93.34,91.18 93.72,90.81
  BOTTOM w0.203: Q8.1 v1(96.82,146.74)
  BOTTOM w0.508: R100.1 100.67,154.52 99.82,153.67 TP37.1 R67.1 93.69,153.67 R83.2
PGOOD2: length 166.5
  LAYER_4 w0.152: v2(90.26,76.26) 89.75,75.74 87.06,75.74 86.75,75.42 86.75,75.06 86.47,74.77 86.27,74.77 86.23,74.74 86.06,74.74 85.75,74.42 85.75,68.94 85.85,68.83
  LAYER_4 w0.203: TP38.1 86.11,7.37 86.11,12.06 86.36,12.32 86.36,12.95 86.11,13.21 86.11,40.77 86.36,41.02 86.36,41.91 86.11,42.16 86.11,68.58 85.85,68.83
  LAYER_6 w0.152: v2(90.26,76.26) 90.78,76.77 91.47,76.77 91.78,77.09 91.78,78.46 92.06,78.74 92.47,78.74 92.78,79.06 92.78,79.46 93.06,79.74 93.45,79.74 93.78,80.07 93.78,88.49 94.06,88.77 94.47,88.77 94.78,89.09 94.78,90.68
  LAYER_6 w0.203: v1(101.6,151.64) 101.6,137.67 93.78,129.85 93.78,91.68 94.78,90.68
  BOTTOM w0.381: 88.14,6.35 TP38.1
  BOTTOM w0.508: R100.2 v1(101.6,151.64) ; R7.2 90.42,7.12 90.47,7.18 Q11.1 ; R7.2 R112.1 ; R7.2 88.14,6.35
PGOOD3: length 85.2
  LAYER_4 w0.152: 91.75,68.71 91.75,74.05 91.76,74.06 91.76,74.46 91.47,74.74 90.78,74.74 v2(90.26,75.26)
  LAYER_4 w0.203: TP39.1 102.87,10.92 102.87,57.4 91.75,68.53 91.75,68.71
  BOTTOM w0.508: TP39.1 97.28,6.35 R5.2 ; R5.2 95,7.12 94.92,7.2 Q13.1 ; R5.2 R112.2
RUN0: length 297.2
  LAYER_4 w0.152: v2(90.26,89.26) 89.75,89.77 89.75,90.45 89.89,90.59 89.89,90.81
  LAYER_4 w0.203: 89.89,90.81 89.89,91.03 90.22,91.36 90.22,95.71 89.28,96.65 89.28,112.27 88.39,113.16 88.39,145.8 v1(88.52,145.92)
  LAYER_4 w0.508: TP32.1 4.32,133.86 4.32,128.07 S1.1
  LAYER_5 w0.203: v1(210.84,145.14) 210.69,145.29 v1(207.68,145.29) 207.64,145.29 207.01,145.92 v1(88.52,145.92) 32.51,145.92
  LAYER_5 w0.254: S1.2 8.38,126.49 8.51,126.49 9.41,125.59 12.18,125.59 32.51,145.92
  BOTTOM w0.203: R172.2 v1(207.68,145.29) ; R177.1 210.99,144.99 v1(210.84,145.14)
  BOTTOM w0.381: S1.1 S1.2 8.25,125.41 7.41,124.56 R129.2 R127.1 ; TP32.1 9.59,137.16 10.44,136.31 R85.1 ; R172.2 R171.1
RUN1: length 433.1
  LAYER_4 w0.381: v1(12.19,138.05) 12.19,126.52 11.2,125.53 10.46,125.53 2.41,117.47 v1(2.41,98.81) 2.41,30.35 2.79,29.97 3.94,29.97 6.98,26.92 9.02,26.92 10.53,25.42 10.53,22.84 9.35,21.67 v1(9.35,21.34)
  LAYER_5 w0.152: v2(91.26,89.26) 90.78,89.74 89.06,89.74 88.75,89.42 88.75,89.06 88.47,88.77 87.06,88.77 86.78,89.06 86.78,89.46 86.5,89.74 81.03,89.74 80.77,89.48
  LAYER_5 w0.203: v1(94.23,144.78) 94.49,144.53 205.87,144.53 ; v1(205.91,144.99) 205.87,144.96 205.87,144.53 ; 205.87,144.53 v1(209.04,144.53) ; 80.77,89.48 80.67,89.38
  LAYER_5 w0.381: 80.67,89.38 79.83,88.54 24.49,88.54 14.22,98.81 v1(2.41,98.81)
  LAYER_5 w0.508: S2.1 4.56,144.4 3.43,145.53 3.43,148.84 5.08,150.5 6.86,150.5 10.03,153.67 TP33.1
  LAYER_6 w0.152: v2(91.26,89.26) 90.78,89.74 90.78,90.46 91.13,90.81
  LAYER_6 w0.203: v1(94.23,144.78) 94.23,139.98 94.41,139.8 94.41,139.34 94.23,139.16 94.23,134.81 91.67,132.25 91.67,97.68 91.74,97.6 91.74,97.14 91.67,97.06 91.67,91.34 91.13,90.81
  BOTTOM w0.203: 11.34,138.05 R85.2 ; 209.72,145.2 D4.C
  BOTTOM w0.381: R135.2 8.04,144.18 S2.2 S2.1 ; R135.2 8.04,141.27 10.58,138.73 10.58,138.63 11.2,138.01 R85.2 ; R135.2 R133.1 ; R173.2 R168.2 209.22,146.9 209.72,146.41 D4.C ; v1(12.19,138.05) 11.34,138.05 ; v1(209.04,144.53) 209.72,145.2
RUN2: length 303.1
  LAYER_4 w0.203: v1(205.11,15.49) 204.81,15.79 v1(201.08,15.79)
  LAYER_4 w0.508: TP34.1 4.61,21.12 4.61,13.47 S3.1
  LAYER_5 w0.203: v1(205.11,15.49) 205.11,16.38 202.18,19.3 171.88,19.3 171.37,18.8 66.67,18.8 62.23,23.24 v1(62.23,25.15)
  LAYER_6 w0.152: 89.75,68.71 89.78,68.74 89.78,70.74 v2(89.26,71.26)
  LAYER_6 w0.203: v1(62.23,25.15) 62.23,25.27 ; 62.23,25.27 61.24,25.27 61.19,25.22 60.73,25.22 60.68,25.27 8.76,25.27 TP34.1 ; 62.23,25.27 72.77,25.27 86.87,39.37 86.87,44.85 88.98,46.96 88.98,46.97 89.75,47.74 89.75,68.71
  BOTTOM w0.203: R169.2 R174.2
  BOTTOM w0.381: R169.2 205.66,13.79 205.11,14.35 v1(205.11,15.49) ; S3.2 7.41,11.47 R138.1 R141.2 5.93,11.01 5.77,11.18 S3.1 ; TP34.1 8.47,23.53 R114.1 R102.2
RUN3: length 322.7
  LAYER_4 w0.508: S4.2 17.78,20.57 TP35.1
  LAYER_5 w0.203: v1(204.09,12.95) 204.09,16.82 202.02,18.9 172.05,18.9 171.54,18.39 66.51,18.39 60.96,23.94 v1(60.96,25.78)
  LAYER_5 w0.381: v1(208.15,12.95) v1(204.09,12.95)
  LAYER_6 w0.152: v2(88.27,71.26) 88.77,70.75 88.77,69.05 88.43,68.71
  LAYER_6 w0.203: 88.43,68.71 87.63,67.9 87.63,62.42 88.27,61.78 88.27,46.82 86.36,44.92 86.36,39.62 72.52,25.78 v1(60.96,25.78) 12.57,25.78 S4.2
  BOTTOM w0.381: S4.1 S4.2 8.04,29.88 R147.2 ; R175.2 208.71,12.4 v1(208.15,12.95) ; R114.2 11.05,25.91 10.03,26.92 8.51,26.92 8.04,27.39 R147.2 ; R147.2 R146.1 ; R170.2 204.09,12.08 v1(204.09,12.95) 202.95,14.1 D6.C
  BOTTOM w0.508: v1(208.15,12.95) 208.15,14.26 R178.1
SCL: length 270.9
  LAYER_4 w0.102: P5.6 214.33,3.09 213.32,4.11 213.32,5.84
  LAYER_4 w0.203: v1(213.23,42.67) 213.36,42.8 213.84,42.8 ; v1(213.23,94.11) 213.66,94.54 ; 213.66,94.54 213.25,94.95 v1(213.25,131.17) 213.32,131.25 213.32,155.59 P4.6 ; 213.66,94.54 213.84,94.36 213.84,42.8 ; P3.B2 235.84,92.02 235.84,128.97 P6.3 ; 213.32,5.84 213.32,5.87 213.36,5.91 213.36,16.83 213.83,17.3 213.83,22.34 213.84,22.36 213.84,42.8
  LAYER_5 w0.203: v1(213.23,94.11) 235.33,94.11 235.84,93.6 235.84,92.02 P3.B2 ; P6.3 v1(213.25,131.17) ; v1(213.23,42.67) TP49.1
  BOTTOM w0.203: R153.1 233.64,41.23 TP49.1 232.2,44.55 232.28,44.64 R152.1
SCL_01: length 286.5
  LAYER_4 w0.152: 92.75,90.81 92.75,89.06 92.47,88.77 92.08,88.77 91.75,88.45 91.75,88.06 91.47,87.77 90.78,87.77 v2(90.26,87.26)
  LAYER_4 w0.203: 92.75,90.81 92.75,91.22 94.49,92.96 94.49,94.36 95.5,95.38 95.5,113.16 93.6,115.06 93.6,139.32 v1(93.85,139.57) ; v1(229.11,44.58) 228.85,44.83 228.85,45.69 228.02,46.53 228.02,49.38 227.2,50.19 227.2,57.02 226.69,57.53 226.69,83.76 227.71,84.78 227.71,86.34 227.43,86.62 227.43,100.27 227.76,100.6 227.76,117.73 228.25,118.22 228.25,135.1 v1(228.22,135.13)
  LAYER_5 w0.203: v1(228.22,135.13) 224.03,139.32 94.11,139.32 v1(93.85,139.57)
  BOTTOM w0.203: R53.1 229.69,44.7 R152.2
SCL_23: length 200.1
  LAYER_3 w0.152: 87.76,68.71 87.76,71.43 88.06,71.74 88.75,71.74 v2(89.26,72.26)
  LAYER_3 w0.203: v1(87.76,24.77) 87.38,25.15 87.38,67.31 87.76,67.69 87.76,68.71
  LAYER_5 w0.203: v1(231.01,39.12) 222.38,39.12 207.9,24.64 v1(87.76,24.77)
  BOTTOM w0.203: R21.1 v1(231.01,39.12) R153.2
SDA: length 240.9
  LAYER_4 w0.102: 211.33,5.84 211.33,4.06 212.33,3.06 P5.4
  LAYER_4 w0.203: 211.45,50.42 211.33,50.29 211.33,13.87 211.76,13.44 211.76,6.78 211.33,6.35 211.33,5.84 ; 211.45,50.42 v1(211.45,50.29) ; 211.45,50.42 211.33,50.55 211.33,118.46 211.51,118.64 211.51,119.1 211.33,119.28 211.33,127.18 ; P6.1 235.2,125.61 235.2,93.38 P3.B1 ; 211.33,127.18 211.63,127.48 211.63,141.2 211.41,141.43 211.41,146.26 211.25,146.41 211.25,147.21 211.32,147.28 211.32,155.59 P4.4 ; 211.33,127.18 v1(211.2,127.18)
  LAYER_5 w0.203: P6.1 v1(211.2,127.18) ; TP48.1 v1(211.45,50.29)
  BOTTOM w0.203: R151.1 232.28,48.26 232.2,48.35 TP48.1 231.35,51.14 R148.1
SDA_01: length 281.5
  LAYER_4 w0.152: 91.97,90.81 91.75,90.58 91.75,89.06 91.47,88.77 90.97,88.77 90.45,88.26 v2(90.26,88.26)
  LAYER_4 w0.203: v1(233.05,54.23) 230,54.23 228.22,56.01 228.22,86.41 227.84,86.79 227.84,100.1 228.22,100.49 228.22,117.47 228.73,117.98 229.22,117.98 229.22,136.03 228.98,136.27 v1(227.96,136.27) ; 91.97,90.81 92.1,90.94 92.1,90.97 92.13,91 92.13,93.52 93.98,95.38 93.98,113.41 92.58,114.81 92.58,138.86 v1(92.13,139.32)
  LAYER_5 w0.203: v1(227.96,136.27) 224.41,139.83 94.69,139.83 94.31,140.21 92.33,140.21 92.13,140 v1(92.13,139.32)
  BOTTOM w0.203: R51.1 v1(233.05,54.23) R148.2
SDA_23: length 223.9
  LAYER_3 w0.152: 86.75,68.71 86.75,72.46 87.06,72.77 87.78,72.77 v2(88.27,73.26)
  LAYER_3 w0.203: 86.75,68.71 86.36,68.32 86.36,45.21 83.06,41.91 83.06,40.64 85.09,38.61 85.09,23.37 v1(85.34,23.11)
  LAYER_4 w0.203: v1(227.96,23.37) 227.96,38.1 229.95,40.08 v1(229.95,47.75)
  LAYER_5 w0.203: v1(227.96,23.37) 227.71,23.62 213.74,23.62 213.36,23.24 211.71,23.24 211.33,23.62 85.85,23.62 v1(85.34,23.11)
  BOTTOM w0.203: R28.1 v1(229.95,47.75) R151.2
SHARE_CLK: length 156
  LAYER_4 w0.203: v1(214.63,15.75) 214.76,15.88 214.76,102.01 213.91,102.86 v1(213.91,147.61)
  LAYER_5 w0.203: TP51.1 224.54,148.72 v1(219.67,143.85)
  BOTTOM w0.203: v1(213.91,147.61) R160.2 215.73,147.61 218.86,144.49 R158.1 v1(219.67,143.85) ; v1(214.63,15.75) 214.63,15.74 214.43,15.53 R159.1
SHARE_CLK_01: length 204.7
  LAYER_5 w0.203: v1(87,143.26) 214.88,143.26 215.99,142.15 v1(218.86,142.15) 219.29,142.58 221.2,142.58 223.99,145.38 v1(231.43,145.38)
  LAYER_6 w0.152: v2(88.27,87.26) 88.08,87.26 87.56,87.77 87.06,87.77 86.78,88.06 86.78,90.81
  LAYER_6 w0.203: 86.78,90.81 86.78,91.38 87,91.59 87,92.41 86.8,92.6 86.8,117.45 86.36,117.89 86.36,138.75 87,139.38 v1(87,143.26)
  BOTTOM w0.203: R65.1 v1(231.43,145.38)
SHARE_CLK_23: length 169.8
  LAYER_4 w0.152: v2(91.26,70.26) 90.78,69.77 90.78,68.71
  LAYER_4 w0.203: v1(99.44,20.7) 99.39,20.75 99.39,42.54 98.21,43.71 98.02,43.71 90.78,50.95 90.78,61.24 90.83,61.29 90.83,63.1 90.78,63.15 90.78,68.71
  LAYER_5 w0.203: v1(99.44,20.7) 100.2,20.7 100.32,20.82 206.01,20.82 207.99,18.84 v1(212.38,18.84)
  BOTTOM w0.203: v1(212.38,18.84) R6.1 R159.2
SYNC: length 154.1
  LAYER_4 w0.203: v1(215.39,13.33) 215.77,13.72 215.77,27.86 215.98,28.07 ; 215.98,28.07 v1(215.9,28.07) ; 215.98,28.07 215.81,28.23 v1(215.81,143.85)
  LAYER_5 w0.203: TP52.1 230.87,28.13 215.96,28.13 v1(215.9,28.07)
  BOTTOM w0.203: v1(215.39,13.33) 218.69,13.33 219.37,12.66 R163.2 R162.1
SYNC_01: length 182.4
  LAYER_5 w0.203: v1(214.94,142.11) 214.33,142.72 207.46,142.72 206.89,142.15 95.08,142.15 94.74,142.49 v1(93.22,142.49)
  LAYER_6 w0.152: v2(91.26,87.26) 90.75,87.77 90.06,87.77 89.78,88.06 89.78,90.46 90.13,90.81
  LAYER_6 w0.203: 90.13,90.81 90.63,91.3 90.63,98.18 91.26,98.81 91.26,132.42 93.22,134.37 v1(93.22,142.49)
  BOTTOM w0.203: v1(214.94,142.11) 215.26,142.11 215.3,142.15 R161.2 R60.1
SYNC_23: length 200.4
  LAYER_4 w0.152: 86.78,68.71 86.78,71.46 87.1,71.77 88.66,71.77 88.78,71.89 88.78,72.77 v2(89.26,73.26)
  LAYER_4 w0.203: v1(87.38,21.34) 86.61,22.1 86.61,40.64 86.87,40.89 86.87,42.04 86.61,42.29 86.61,68.54 86.78,68.71
  LAYER_5 w0.203: v1(87.38,21.34) 87.55,21.26 210.77,21.26 217.83,14.2 218.56,14.2 219.81,12.95 219.81,12.79 220.89,11.71 v1(220.89,10.45)
  BOTTOM w0.203: R16.1 226.19,9.78 225.81,9.4 221.11,9.4 220.89,9.61 v1(220.89,10.45)
UNNAMED_2_ADLTM4683_I1_ASEL01: length 31.3
  LAYER_4 w0.152: 90.82,90.81 90.75,90.73 90.75,89.06 90.47,88.77 89.75,88.77 v2(89.26,89.26)
  LAYER_4 w0.203: v1(89.53,117.35) 89.28,117.09 89.28,113.79 90.58,112.5 90.58,96.61 91.31,95.88 91.31,91.3 90.82,90.81
UNNAMED_2_ADLTM4683_I1_ASEL23: length 33
  LAYER_4 w0.152: v2(90.26,70.26) 89.78,69.77 89.78,68.71
  LAYER_4 w0.203: v1(98.42,42.08) 97.06,42.08 89.78,49.35 89.78,61.39 90.02,61.62 90.02,62.76 89.78,63 89.78,68.71
UNNAMED_2_ADLTM4683_I1_FSWPH01CFG: length 31
  LAYER_4 w0.152: 89.46,90.81 89.46,90.69 89.26,90.49 v2(89.26,90.26)
  LAYER_4 w0.203: 89.46,90.81 89.46,92.97 88.87,93.55 88.87,112.06 85.72,115.21 v1(85.72,118.14)
  BOTTOM w0.203: R50.2 v1(85.72,118.14) R59.1
UNNAMED_2_ADLTM4683_I1_FSWPH23CFG: length 33.2
  LAYER_4 w0.152: 88.78,68.71 88.78,69.77 v2(89.26,70.26)
  LAYER_4 w0.203: 88.78,68.71 88.09,68.01 88.09,66.86 88.14,66.81 88.14,65.78 88.09,65.73 88.09,65.26 88.14,65.21 88.14,63.44 88.82,62.75 88.88,62.75 89.2,62.42 89.2,61.96 88.88,61.63 88.82,61.63 88.78,61.59 88.78,46.35 92.71,42.41 v1(92.71,41.41)
  BOTTOM w0.203: R15.2 92.71,41.4 v1(92.71,41.41) 92.71,42.07 R27.1
UNNAMED_2_ADLTM4683_I1_IIN01: length 36.8
  TOP w0.254: U1.J10 v2(90.68,82.67)
  LAYER_4 w0.203: v1(67.01,93.1) v1(67.01,83.82)
  LAYER_5 w0.152: 80.77,82.68 81,82.68 81.06,82.74 87.58,82.74 87.65,82.67 89,82.67 89.06,82.74 89.47,82.74 89.53,82.67 v2(90.68,82.67)
  LAYER_5 w0.203: 80.77,82.68 72.14,82.68 70.99,83.82 v1(67.01,83.82)
  BOTTOM w0.203: R37.1 67.31,95.11 67.01,94.81 C28.2 v1(67.01,93.1)
UNNAMED_2_ADLTM4683_I1_IIN01_1: length 37.1
  LAYER_4 w0.203: v1(65.41,93.1) v1(65.41,84.33)
  LAYER_5 w0.152: 80.77,84.07 81.06,83.77 89.93,83.77 90.1,83.6 90.1,83.42 v2(90.26,83.26)
  LAYER_5 w0.203: 80.77,84.07 80.74,84.1 71.29,84.1 70.63,84.76 65.84,84.76 v1(65.41,84.33)
  BOTTOM w0.203: v1(65.41,93.1) C28.1 R34.1
UNNAMED_2_ADLTM4683_I1_IIN23: length 35.9
  LAYER_3 w0.152: 80.9,75.82 80.94,75.77 88.78,75.77 v2(89.26,76.26)
  LAYER_3 w0.203: 80.9,75.82 80.68,76.04 74.15,76.04 73.93,75.82 v1(65.53,75.82)
  LAYER_4 w0.203: v1(65.49,66.76) 65.49,75.78 v1(65.53,75.82)
  BOTTOM w0.203: R38.1 65.41,64.72 65.49,64.81 C33.1 v1(65.49,66.76)
UNNAMED_2_ADLTM4683_I1_IIN23_1: length 35.7
  LAYER_3 w0.152: v2(89.26,77.26) 88.78,77.74 81.06,77.74 80.91,77.58 80.89,77.58 80.78,77.48 80.77,77.48
  LAYER_3 w0.203: v1(67.09,77.05) 67.53,77.48 80.77,77.48
  LAYER_4 w0.203: v1(67.09,66.76) v1(67.09,77.05)
  BOTTOM w0.203: v1(67.09,66.76) C33.2 67.09,64.93 67.31,64.72 R41.1
UNNAMED_2_ADLTM4683_I1_RUNP: length 117.7
  TOP w0.152: U1.N11 v2(91.27,78.26)
  LAYER_3 w0.152: v2(91.27,78.26) 90.75,78.78 90.75,80.62 90.6,80.77 80.77,80.77
  LAYER_3 w0.203: 80.77,80.77 80.72,80.77 80.59,80.64 75.62,80.64 75.34,80.92 v1(75.31,80.92)
  LAYER_6 w0.203: P1.2 30.23,154.31 72.01,112.52 72.01,86.36 73.91,84.45 73.91,83.49 75.31,82.09 v1(75.31,80.92)
  BOTTOM w0.508: R52.1 P1.2
UNNAMED_2_ADLTM4683_I1_TSNS0: length 23.7
  LAYER_5 w0.152: 80.77,87.74 89.47,87.74 89.78,87.42 89.78,87.06 90.06,86.77 90.75,86.77 v2(91.26,86.26)
  LAYER_5 w0.203: 80.77,87.74 80.34,87.74 80.11,87.5 v1(68.45,87.5)
UNNAMED_2_ADLTM4683_I1_TSNS1: length 22.4
  LAYER_5 w0.152: v2(90.26,86.26) 89.76,85.75 80.77,85.75
  LAYER_5 w0.203: v1(68.45,85.85) 69.06,85.85 69.57,85.34 80.31,85.34 80.72,85.75 80.77,85.75
UNNAMED_2_ADLTM4683_I1_TSNS2: length 14.4
  LAYER_5 w0.152: 80.77,73.79 81.05,73.79 81.06,73.77 87.78,73.77 v2(88.27,74.26)
  LAYER_5 w0.203: v1(74.04,73.79) 80.77,73.79
UNNAMED_2_ADLTM4683_I1_TSNS3: length 16.5
  LAYER_5 w0.152: 80.77,72.77 88.46,72.77 88.75,73.06 88.75,73.74 v2(89.26,74.26)
  LAYER_5 w0.203: v1(74.04,72.14) 79.88,72.14 80.52,72.77 80.77,72.77
UNNAMED_2_ADLTM4683_I1_VINVBIAS: length 15.6
  LAYER_3 w0.152: v2(89.26,78.26) 88.78,78.74 81.06,78.74 80.94,78.61 80.77,78.61
  LAYER_3 w0.203: 80.77,78.61 75.4,78.61 v1(74.38,79.63)
UNNAMED_2_ADLTM4683_I1_WP01: length 99.9
  LAYER_3 w0.152: v2(89.26,86.26) 88.75,85.74 80.77,85.74
  LAYER_3 w0.203: v1(73.53,86.36) 74.55,85.34 80.31,85.34 80.71,85.74 80.77,85.74
  LAYER_6 w0.203: v1(73.53,86.36) 74.03,86.86 74.03,117.94 64.59,127.38 64.39,127.38 P2.2
UNNAMED_2_ADLTM4683_I1_WP23: length 102.9
  LAYER_6 w0.152: v2(91.26,71.26) 90.78,70.77 90.78,68.71
  LAYER_6 w0.203: P17.2 37.56,8.89 63.25,8.89 90.78,36.43 90.78,40.63 90.25,41.17 90.25,41.63 90.78,42.17 90.78,68.71
UNNAMED_2_CAP_I53_N2: length 2.6
  TOP w0.508: C12.2 77.33,70.7 77.28,70.75 R29.1
UNNAMED_2_CAP_I70_N2: length 2.1
  TOP w0.508: C17.2 77.33,77.64 77.28,77.59 R30.1
UNNAMED_2_CAP_I238_N2: length 2.3
  TOP w0.508: C55.2 77.33,88.25 77.28,88.2 R42.1
UNNAMED_2_CAP_I249_N2: length 2.1
  TOP w0.508: C56.2 77.28,81.33 R44.1
UNNAMED_2_CN3P_I72_N1: length 2.3
  BOTTOM w0.508: R3.1 P17.1
UNNAMED_2_CN3P_I268_N1: length 2.7
  BOTTOM w0.381: R70.1 P2.1
UNNAMED_2_CN3P_I335_N1: length 2.3
  BOTTOM w0.508: R43.1 P1.1
UNNAMED_4_CAP_I413_N2: length 1.5
  BOTTOM w0.381: R129.1 C88.2
UNNAMED_4_CAP_I415_N2: length 1.5
  BOTTOM w0.381: R135.1 C89.2
UNNAMED_4_CAP_I420_N2: length 1.5
  BOTTOM w0.381: R147.1 C91.2
UNNAMED_4_CAP_I427_N2: length 8.9
  BOTTOM w0.508: C90.2 10.63,9.23 9.92,8.52 4.85,8.52 4.23,9.14 R141.1
UNNAMED_4_CNBNC5P_I301_CNTR: length 17.8
  LAYER_4 w0.254: v1(172.85,138.68) 173.99,138.68 175.01,139.7 175.01,144.14 178.44,147.57 J1.1
  BOTTOM w0.203: R74.1 172.59,138.43 v1(172.85,138.68)
UNNAMED_4_CNBNC5P_I354_CNTR: length 16.1
  LAYER_4 w0.254: v1(167.77,15.88) 169.16,15.88 169.93,15.11 169.93,14.09 176.52,7.49 J2.1
  BOTTOM w0.254: R75.1 v1(167.77,15.88)
UNNAMED_4_CNTP1P_I307_N1: length 39.8
  LAYER_4 w0.203: TP22.1 148.59,146.43 v1(159,136.02)
  BOTTOM w0.203: 159,134.37 Q1.1
  BOTTOM w0.381: R72.2 TP22.1
  BOTTOM w0.508: Q3.1 166.5,134.24 166.5,132.72 165.99,132.21 159.51,132.21 159,132.72 Q1.1 ; v1(159,136.02) 159,134.37
UNNAMED_4_CNTP1P_I352_N1: length 42.2
  LAYER_4 w0.203: v1(163.58,22.86) 148.59,7.87 TP3.1
  BOTTOM w0.203: TP3.1 R73.2 ; v1(163.58,22.86) 163.58,22.86 Q4.1
  BOTTOM w0.508: Q2.1 171.2,25.15 171.2,26.67 170.69,27.18 164.09,27.18 163.58,26.67 Q4.1
UNNAMED_4_DIOLED_I553_N: length 1.7
  TOP w0.203: v1(194.06,9.02) DS9.C
  BOTTOM w0.203: R144.2 v1(194.06,9.02)
UNNAMED_4_DIOLED_I553_P: length 3
  TOP w0.203: DS9.A v1(192.66,11.47)
  BOTTOM w0.203: Q15.3 191.9,10.55 192.66,11.3 v1(192.66,11.47)
UNNAMED_4_DIOLED_I558_N: length 4
  TOP w0.508: DS7.C 96.34,10.82 96.34,11.1 v1(95.76,11.68)
  BOTTOM w0.508: v1(95.76,11.68) 95.26,12.18 Q13.3
UNNAMED_4_DIOLED_I558_P: length 0.9
  BOTTOM w0.203: v1(98.58,10.16) 98.01,10.16 R139.1
UNNAMED_4_DIOLED_I562_N: length 3.9
  TOP w0.381: v1(87.5,11.18) 87.5,11.15 DS5.C
  BOTTOM w0.381: Q11.3 88.51,12.18 v1(87.5,11.18)
UNNAMED_4_DIOLED_I562_P: length 0.9
  BOTTOM w0.203: v1(84.94,10.16) 85.52,10.16 R136.1
UNNAMED_4_DIOLED_I566_N: length 3.9
  TOP w0.381: DS3.C v1(98.17,148.97)
  BOTTOM w0.381: Q8.3 97.79,150.09 98.17,149.71 v1(98.17,148.97)
UNNAMED_4_DIOLED_I566_P: length 2.8
  TOP w0.381: DS3.A 100.48,149.89 100.58,149.99 v1(100.58,150.11)
  BOTTOM w0.381: R130.1 99.69,149.83 99.97,150.11 v1(100.58,150.11)
UNNAMED_4_DIOLED_I570_N: length 3.5
  TOP w0.381: v1(89.03,149.1) 88.9,148.97 DS1.C
  BOTTOM w0.381: v1(89.03,149.1) 90.02,150.09 Q5.3
UNNAMED_4_DIOLED_I570_P: length 2.1
  TOP w0.381: v1(86.61,149.73) 86.61,149.22 86.84,149 DS1.A
  BOTTOM w0.381: R124.1 87.08,149.73 v1(86.61,149.73)
UNNAMED_4_DIOLED_I575_N:
  vias: v1(228.75,99.44)
UNNAMED_4_DIOLED_I575_P: length 2.9
  TOP w0.203: v1(226.82,100.58) 226.82,99.8 227.16,99.45 DS11.A
  BOTTOM w0.203: v1(226.82,100.58) 226.81,100.59 Q17.3
UNNAMED_4_DIOLED_I576_N:
  vias: v1(228.81,109.6)
UNNAMED_4_DIOLED_I576_P: length 3.5
  TOP w0.203: v1(226.57,110.87) 227.01,110.43 DS10.A
  BOTTOM w0.203: Q16.3 226.81,111.12 v1(226.57,110.87)
UNNAMED_4_DIOLED_I577_N: length 1.7
  TOP w0.203: v1(228.98,117.35) 228.77,117.13 DS8.C
  BOTTOM w0.203: R182.2 228.81,117.18 v1(228.98,117.35)
UNNAMED_4_DIOLED_I577_P: length 3.6
  TOP w0.203: v1(226.61,117.73) 226.57,117.68 226.57,117.09 227.08,116.59 DS8.A
  BOTTOM w0.203: Q14.3 226.81,117.93 v1(226.61,117.73)
UNNAMED_4_DIOLED_I578_N: length 1.7
  TOP w0.203: DS6.C v1(229.62,139.06)
  BOTTOM w0.203: v1(229.62,139.06) R181.2
UNNAMED_4_DIOLED_I578_P: length 3.1
  TOP w0.203: DS6.A 227.16,139.73 v1(226.81,140.08)
  BOTTOM w0.203: Q12.3 v1(226.81,140.08)
UNNAMED_4_DIOLED_I579_N:
  vias: v1(194.06,147.74)
UNNAMED_4_DIOLED_I579_P: length 4.7
  TOP w0.508: v1(193.04,149.35) 193.07,149.33 DS4.A
  LAYER_5 w0.508: v1(189.6,148.72) 190.5,148.72 191.13,149.35 v1(193.04,149.35)
UNNAMED_4_RES_I402_N2: length 4.3
  BOTTOM w0.508: R126.2 R128.2 80.4,147.53 80.1,147.83 80.09,147.82 Q7.1
UNNAMED_4_RES_I408_N2: length 4
  BOTTOM w0.508: Q10.1 79.22,9.95 R132.2 R134.2
UNNAMED_5_CN4P_I53_N4: length 4.8
  BOTTOM w0.254: D2.A D1.A 232.25,133.48 232.56,133.17 P6.4
UNNAMED_5_CN12PABV2_I55_N4: length 7.6
  LAYER_5 w0.102: 230.38,87.78 233.73,87.78 234.58,86.94 P3.B4
  LAYER_5 w0.203: v1(228.57,87.12) 229.24,87.78 230.38,87.78
  BOTTOM w0.203: R149.1 228.6,87.1 v1(228.57,87.12)
UNNAMED_5_CN12PABV2_I176_N5: length 4
  BOTTOM w0.203: R150.1 P3.A5
UNNAMED_5_CN14P_I156_N2: length 186.7
  LAYER_4 w0.203: 209.25,9.06 v1(209.3,9.02) ; 209.25,9.06 209.25,3.7 210.13,2.83 P5.2 ; 209.25,9.06 209.3,9.1 209.3,12.93 208.86,13.36 208.86,86.28 v1(208.79,86.36) 208.53,86.61 208.53,143.64 208.28,143.89 208.28,145.8 208.53,146.05 208.53,149.35 ; P4.2 208.53,154.81 208.53,149.35 ; v1(209.22,149.31) 208.57,149.31 208.53,149.35
  LAYER_5 w0.203: v1(208.79,86.36) v1(226.9,86.36)
  BOTTOM w0.203: v1(209.22,149.31) 209.22,149.81 208.86,150.16 206.36,150.16 206.16,149.96 R171.2 ; R150.2 v1(226.9,86.36) ; R169.1 205.66,9.45 206.1,9.02 v1(209.3,9.02)
  BOTTOM w0.381: R170.1 R169.1
UNNAMED_5_CN14P_I156_N5: length 151.6
  LAYER_4 w0.203: P4.5 214.33,150.42 v1(214.5,150.24) 214.5,142.69 214.38,142.56 214.38,125.9 215.26,125.01 215.26,14.35 214.83,13.92 214.83,12.68 214.33,12.18 P5.5
  BOTTOM w0.203: v1(214.5,150.24) 214.67,150.07 R160.1
UNNAMED_5_CN14P_I156_N7: length 150.8
  LAYER_4 w0.203: P5.7 216.92,5.41 216.92,26.92 217.17,27.18 217.17,28.96 216.92,29.21 216.92,57.4 217.3,57.78 217.3,58.8 216.92,59.18 216.92,154 P4.7
UNNAMED_5_CN14P_I156_N9: length 152.4
  LAYER_4 w0.203: 219.08,10.12 218.74,9.78 218.74,7.35 218.33,6.94 P5.9 ; 219.08,10.12 219.08,138.43 218.06,139.45 218.06,143.38 218.89,144.21 218.89,147.92 219.08,148.12 219.08,153.84 P4.9 ; 219.08,10.12 219.33,9.87 v1(219.33,9.78)
  BOTTOM w0.203: v1(219.33,9.78) 219.37,9.82 R163.1
UNNAMED_5_CN14P_I156_N10: length 157.3
  LAYER_4 w0.102: 217.35,5.84 217.35,3.89 218.33,2.9 P5.10
  LAYER_4 w0.203: 217.35,5.84 217.35,6.53 218.34,7.52 218.34,138.56 217.42,139.47 217.42,143.61 218.34,144.53 v1(218.34,150.5) 218.34,153.17 217.34,154.17 217.34,155.59 P4.10
  BOTTOM w0.203: v1(218.34,150.5) 218.33,150.48 R154.2
UNNAMED_5_CN14P_I156_N14: length 157.2
  LAYER_4 w0.508: P5.14 P5.13 224.28,6.78 v1(224.28,10.58) 224.28,15.37 222.12,17.53 222.12,153.15 222.35,153.38 P4.13 P4.14
  BOTTOM w0.508: R155.2 v1(224.28,10.58)
VBIAS: length 102.8
  TOP w0.254: U1.N10 v2(90.7,77.82)
  LAYER_3 w0.152: 80.77,79.77 89.76,79.77 89.92,79.62 89.92,78.6 v2(90.7,77.82)
  LAYER_3 w0.203: v1(77.98,79.76) 79.1,79.76 79.11,79.77 80.77,79.77
  LAYER_6 w0.203: v1(77.98,79.76) 77.98,81.86 76.45,83.39 76.45,120.52 46.99,149.99 TP31.1
  BOTTOM w0.254: C44.2 78.11,79.63 v1(77.98,79.76)
